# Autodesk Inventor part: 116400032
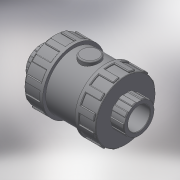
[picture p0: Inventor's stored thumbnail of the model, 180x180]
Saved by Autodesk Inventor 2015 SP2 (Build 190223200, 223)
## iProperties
Created: 2017-11
Part Number: 116400032
Material: Generic
Description: PLASSON FOOT VALVE CEM PVC 32
Document SubType Name: Modeling
Designer: KIM
Density: 1 g/cm^3
Appearance: Default
Author: KIM
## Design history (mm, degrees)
derived "116400 - 116000.ipt"
feature "Solid1::116400 - 116000.ipt"
tag "TaggingFeature1"
body "Solid1"
other parameters: "d0" = 102, "d1" = 32, "d2" = 66, "d3" = 22, "d4" = 25.6, "d5" = 15.4, "d7" = 44.8, "d8" = 59.4, "d13" = 0.96, "d23" = 22, "d24" = 63.36, "d25" = 0.64, "d26" = 0.96, "d27" = 9.9, "d28" = 4.95, "d29" = 16.5, "d30" = 0, "d35" = 0.96, "d39" = 33, "d45" = 360 deg, "d47" = 0.64, "d50" = 33, "d51" = 19.8, "d53" = 0, "d54" = 1.32, "d56" = 6.4, "d57" = 3.2, "d59" = 0, "d60" = 0.96, "d62" = 360 deg, "d_" = 32, "l_" = 22, "H_" = 102, "K_" = 66
